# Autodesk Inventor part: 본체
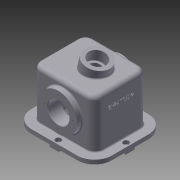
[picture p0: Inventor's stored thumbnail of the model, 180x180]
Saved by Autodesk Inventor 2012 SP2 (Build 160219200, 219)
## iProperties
Created: 2014-11
Part Number: 본체
Material: 알루미늄-6061
Document SubType Name: Modeling
Designer: cad-man
Density: 2.71 g/cm^3
Mass: 2852 g
Surface Area: 2105.51 cm^2
Volume: 1052.4 cm^3
Author: cad-man
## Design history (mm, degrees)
sketch "스케치2"
  geometry: L1 (-98, 87)-(98, 87); L2 (98, 87)-(98, -87); L3 (98, -87)-(-98, -87); L4 (-98, -87)-(-98, 87); 3 further points
  constraints: 8 end point, 2 midpoint, 2 parallel, 1 horizontal, 1 horizontal alignment, 1 perpendicular, 1 vertical alignment
  dimensions: "d0" = 196 distance of L2.end L3.end; "d1" = 174 distance of L1.end L2.end
extrude "돌출1" new body sketch "스케치2" distance "d2" = 10; taper "d3" = 0 deg
sketch "스케치3"
  geometry: L1 (-76, 65)-(76, 65); L2 (76, 65)-(76, -65); L3 (76, -65)-(-76, -65); L4 (-76, -65)-(-76, 65); 3 further points
  constraints: 8 end point, 2 midpoint, 2 parallel, 1 horizontal, 1 horizontal alignment, 1 perpendicular, 1 vertical alignment
  dimensions: "d4" = 152 distance of L2.end L3.end; "d5" = 130 distance of L3.end L1.start
extrude "돌출2" join sketch "스케치3" distance "d6" = 118; taper "d7" = 0 deg
sketch "스케치4"
  geometry: L1 (98, -87)-(98, 87) reference; L2 (98, 11)-(78, 11); L3 (78, 11)-(78, -11); L4 (78, -11)-(98, -11); L5 (98, -11)-(98, 11); 2 further points
  constraints: 8 end point, 2 parallel, 1 horizontal, 1 horizontal alignment, 1 midpoint, 1 perpendicular, 1 point on line
  dimensions: "d10" = 20 distance of L4.end L3.end; "d11" = 22 distance of L3.end L2.end
extrude "돌출3" join sketch "스케치4" distance "d12" = 5; taper "d13" = 0 deg
sketch "스케치12"
  geometry: 2 further points
  constraints: 1 horizontal alignment
  dimensions: "d60" = 88 distance of point (0, 0) point (-88, 0)
hole "구멍4" sketch "스케치12" at (-88, 0) diameter "d61" = 9; stored, may be unused: countersink angle "d65" = 90 deg, drill point angle "d67" = 118 deg; dims "d62" = 6, "d63" = 14, "d64" = 8.6, "d66" = 86
sketch "스케치5"
  geometry: L1 (-98, -87)-(98, -87) reference; L2 (-11, -87)-(11, -87); L3 (11, -87)-(11, -67); L4 (11, -67)-(-11, -67); L5 (-11, -67)-(-11, -87); 2 further points
  constraints: 8 end point, 2 parallel, 1 horizontal, 1 midpoint, 1 perpendicular, 1 point on line, 1 vertical alignment
  dimensions: "d14" = 22 distance of L4.end L3.end; "d15" = 20 distance of L3.end L2.end
extrude "돌출4" join sketch "스케치5" distance "d16" = 5; taper "d17" = 0 deg
sketch "스케치6"
  geometry: L1 (-11, 0)-(11, 0) reference; L2 (-76, 10)-(-76, 128) reference; L3 (76, 10)-(76, 128) reference; L4 (0, 68)-(-76, 68); L5 (0, 68)-(-17.88, 152.121); L6 (-17.88, 152.121)-(12.442, 158.566); L7 (12.442, 158.566)-(30.323, 74.445); L8 (30.323, 74.445)-(0, 68); 1 further point
  constraints: 10 end point, 2 parallel, 2 perpendicular, 1 point on line, 1 vertical alignment
  dimensions: "d18" = 68 distance from line of L1 L4.start; "d19" = 86 distance of L4.start L5.end; "d20" = 78 deg angle of L4 L5; "d21" = 62 diameter of L7 L5
revolve "회전1" sketch "스케치6" stored, may be unused: angle "d22" = 90 deg
sketch "스케치8"
  geometry: L1 (-66, 55)-(66, 55); L2 (66, 55)-(66, -55); L3 (66, -55)-(-66, -55); L4 (-66, -55)-(-66, 55); 3 further points
  constraints: 8 end point, 2 midpoint, 2 parallel, 1 horizontal, 1 horizontal alignment, 1 perpendicular, 1 vertical alignment
  dimensions: "d23" = 132 distance of L2.end L3.end; "d24" = 110 distance of L1.end L2.end
extrude "돌출5" cut sketch "스케치8" distance "d25" = 118; taper "d26" = 0 deg
sketch "스케치10"
  geometry: L1 (-65, 10)-(-65, 128) reference; L2 (55, 0)-(-55, 0) reference; L3 (0, 68)-(-65, 68); L4 (-65, 113.5)-(-77, 113.5); L5 (-77, 113.5)-(-77, 68); L6 (-77, 68)-(-65, 68); L7 (-55, 0)-(-55, 118) reference; L8 (-65, 113.5)-(-55, 113.5); L9 (-55, 113.5)-(-45, 103.5); L10 (-45, 103.5)-(-45, 68); 2 further points
  constraints: 14 end point, 4 point on line, 3 perpendicular, 2 horizontal, 1 collinear, 1 midpoint, 1 vertical alignment
  dimensions: "d27" = 68 distance between parallel lines of L2 L3; "d28" = 91 diameter of L4 L3; "d29" = 12 distance of L4.start L4.end; "d30" = 10 distance between parallel lines of L10 L7; "d31" = 45 deg angle of L7 L9
revolve "회전2" sketch "스케치10" stored, may be unused: angle "d32" = 90 deg
hole "구멍1" diameter "d35" = 52; stored, may be unused: countersink angle "d39" = 90 deg, drill point angle "d41" = 118 deg; dims "d33" = 10, "d34" = 10, "d36" = 6, "d37" = 42, "d38" = 25, "d40" = 32
hole "구멍2" diameter "d44" = 52; stored, may be unused: countersink angle "d48" = 90 deg, drill point angle "d50" = 118 deg; dims "d42" = 10, "d43" = 10, "d45" = 6, "d46" = 42, "d47" = 25, "d49" = 32
hole "구멍3" diameter "d53" = 30; stored, may be unused: countersink angle "d57" = 90 deg, drill point angle "d59" = 118 deg; dims "d51" = 10, "d52" = 10, "d54" = 6, "d55" = 42, "d56" = 25, "d58" = 86
sketch "스케치13"
  geometry: L1 (-98, 87)-(98, 87) reference; L2 (98, -87)-(-98, -87) reference; C1 r 7 at (-88, 0) reference; 4 further points
  constraints: 2 vertical alignment, 1 horizontal alignment
  dimensions: "d68" = 176 distance of point (88, 0) C1.centre; "d69" = 10 distance from line of L1 point (0, 77); "d70" = 10 distance from line of L2 point (0, -77)
hole "구멍5" sketch "스케치13" at (88, 0), (0, 77), (0, -77) diameter "d71" = 9; stored, may be unused: countersink angle "d75" = 90 deg, drill point angle "d77" = 118 deg; dims "d72" = 6, "d73" = 14, "d74" = 8.6, "d76" = 86
sketch "스케치14"
  geometry: L1 (0, 152)-(0, -22) reference; 3 further points
  constraints: 1 horizontal alignment, 1 midpoint, 1 other
  dimensions: "d78" = 92 distance of point (10, 65) point (-82, 65)
feature "엠보싱1" sketch "스케치14" dims "d0" = 196, "d1" = 174, "d10" = 20, "d11" = 22, "d79" = 1, "d80" = 0
sketch "스케치15" dims "d81" = 70
  geometry: C1 r 26 at (0, 0) reference; C2 r 45.5 at (0, 0) reference; 3 further points
  constraints: 2 vertical alignment, 1 coincident, 2 other
hole "구멍6" sketch "스케치15" at (0, 35) diameter "d82" = 3.459; stored, may be unused: countersink angle "d86" = 90 deg, drill point angle "d88" = 118 deg; dims "d83" = 13, "d84" = 14, "d85" = 8.6, "d87" = 16
fillet "모깎기1" dims "d92" = 20
fillet "모깎기2" dims "d93" = 10
fillet "모깎기3" dims "d94" = 3, "d95" = 42
fillet "모깎기4" dims "d96" = 3
fillet "모깎기5" dims "d97" = 3
chamfer "모따기1" distance "d98" = 1; stored, may be unused: second distance "d99" = 2, angle "d100" = 45 deg
node "솔리드1"
mirror "대칭1"
mirror "대칭2"
mirror "대칭3"
pattern_circular "원형 패턴1" dims angle "d90" = 360 deg
mirror "대칭4"
